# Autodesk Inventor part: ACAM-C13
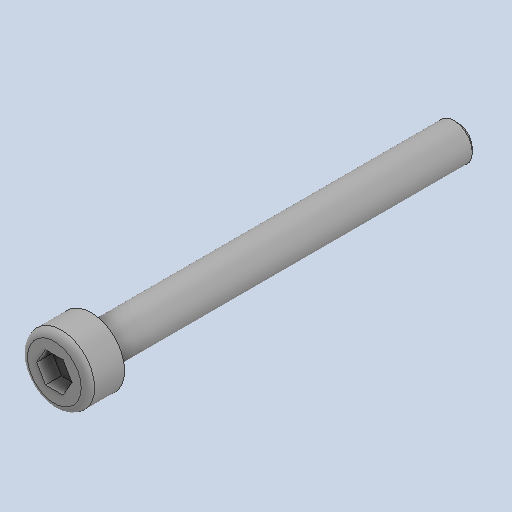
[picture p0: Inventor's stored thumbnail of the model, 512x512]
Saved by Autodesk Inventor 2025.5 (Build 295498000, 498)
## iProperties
Created: 2020-02
Part Number: ACAM-C13
Material: Genérico
Description: Tornillo Allen M3×30
Document SubType Name: Modeling
Designer: Luis M
Authority: Unknown
Density: 1 g/cm^3
Appearance: Valor por defecto
Sending System: FreeCAD
Preprocessor: Open CASCADE STEP processor 7.3
Material_BOM: Por especificar
Proceso_BOM: Comercial
Title: C:/Users/Antonio/Desktop/screws/hex_socket_cylindrical_head_M3x30.step
Author: Author
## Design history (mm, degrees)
feature "Base1"
node "Sólido1"
